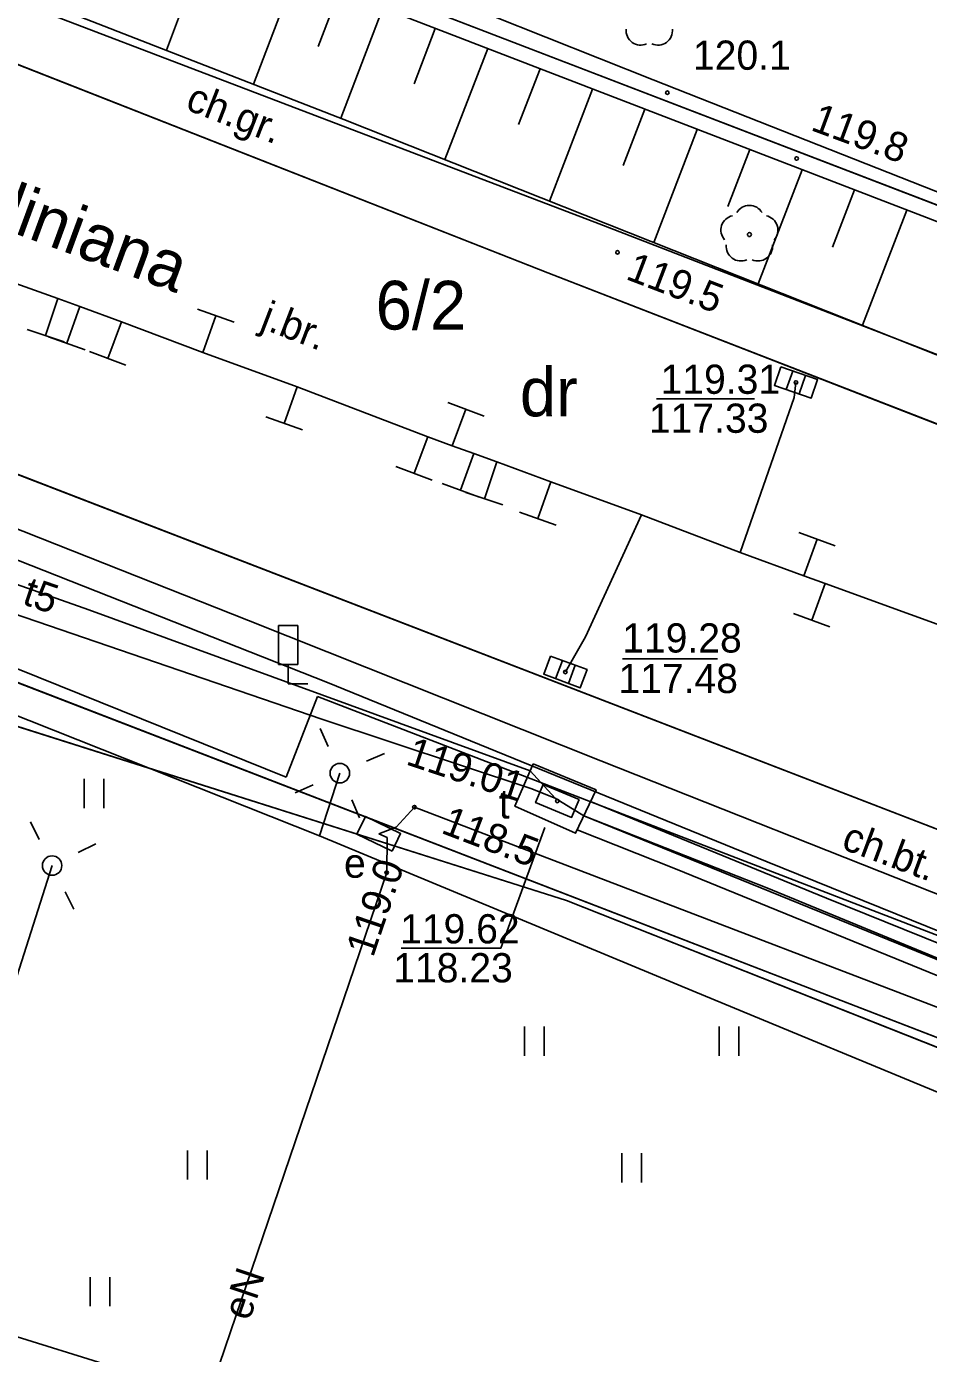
# Model space of a CAD drawing. Extents: x 6432121 to 6432331, y 5662538 to 5662686.
# Drawn here: x 6432202.58 to 6432225.74, y 5662569.04 to 5662603.09 of the extents above; entities that cross this region are included whole.
import ezdxf

# ---------------------------------------------------------------- set-up
doc = ezdxf.new("R2010")
doc.units = 0
for name, color, linetype in [('Warstwa 1', 7, 'Continuous'), ('Warstwa 10', 7, 'Continuous'), ('Warstwa 11', 7, 'Continuous'), ('Warstwa 12', 7, 'Continuous'), ('Warstwa 13', 7, 'Continuous'), ('Warstwa 14', 7, 'Continuous'), ('Warstwa 15', 7, 'Continuous'), ('Warstwa 16', 7, 'Continuous'), ('Warstwa 19', 7, 'Continuous'), ('Warstwa 2', 7, 'Continuous'), ('Warstwa 20', 7, 'Continuous'), ('Warstwa 21', 7, 'Continuous'), ('Warstwa 30', 7, 'Continuous'), ('Warstwa 4', 7, 'Continuous'), ('Warstwa 5', 7, 'Continuous'), ('Warstwa 6', 7, 'Continuous'), ('Warstwa 61', 7, 'Continuous'), ('Warstwa 8', 7, 'Continuous'), ('Warstwa 9', 7, 'Continuous')]:
    doc.layers.add(name, color=color, linetype=linetype)

msp = doc.modelspace()

# ---------------------------------------------------------------- linework, layer by layer
at = {"layer": 'Warstwa 1'}
for p, q in [((6432180.9, 5662615.82), (6432259.074, 5662585.787)), ((6432180.9, 5662615.82), (6432259.074, 5662585.787)), ((6432155.186, 5662604.45), (6432246.621, 5662569.177)), ((6432155.186, 5662604.45), (6432246.621, 5662569.177))]:
    msp.add_line(p, q, dxfattribs=at)
at = {"layer": 'Warstwa 10'}
for p, q in [((6432167.648, 5662617.501), (6432210.732, 5662600.706)), ((6432207.218, 5662605.272), (6432206.177, 5662602.481)), ((6432209.475, 5662604.416), (6432208.412, 5662601.611)), ((6432210.603, 5662603.989), (6432210.068, 5662602.581)), ((6432211.732, 5662603.561), (6432210.651, 5662600.738)), ((6432211.732, 5662603.561), (6432241.32, 5662592.163)), ((6432213.076, 5662603.042), (6432212.532, 5662601.625)), ((6432214.421, 5662602.525), (6432213.323, 5662599.677)), ((6432215.767, 5662602.007), (6432215.215, 5662600.576)), ((6432217.112, 5662601.488), (6432216.004, 5662598.614)), ((6432218.456, 5662600.971), (6432217.9, 5662599.527)), ((6432210.732, 5662600.706), (6432240.306, 5662588.971)), ((6432219.801, 5662600.453), (6432218.683, 5662597.551)), ((6432221.146, 5662599.934), (6432220.584, 5662598.477)), ((6432222.491, 5662599.416), (6432221.362, 5662596.487)), ((6432223.835, 5662598.897), (6432223.269, 5662597.426)), ((6432225.181, 5662598.38), (6432224.042, 5662595.424))]:
    msp.add_line(p, q, dxfattribs=at)
at = {"layer": 'Warstwa 11'}
msp.add_circle((6432221.139, 5662597.753), 0.05, dxfattribs=at)
for centre, start, end in [((6432218.35, 5662602.989), 174.1471, 293.8529), ((6432218.79, 5662602.989), 246.1471, 5.8529), ((6432221.139, 5662598.128), 30.1471, 149.8529), ((6432220.782, 5662597.869), 102.1471, 221.8529), ((6432221.496, 5662597.869), 318.1471, 77.8529), ((6432220.919, 5662597.45), 174.1471, 293.8529), ((6432221.359, 5662597.45), 246.1471, 5.8529)]:
    msp.add_arc(centre, 0.375, start, end, dxfattribs=at)
at = {"layer": 'Warstwa 12'}
for points in [[(6432151.934, 5662659.962), (6432163.647, 5662662.364), (6432165.031, 5662661.271), (6432166.026, 5662656.887), (6432167.998, 5662648.227), (6432170.198, 5662638.637), (6432172.215, 5662629.789), (6432174.2, 5662621.336), (6432174.764, 5662618.709), (6432176.004, 5662617.499), (6432181.388, 5662615.664), (6432187.493, 5662613.63), (6432194.563, 5662611.29), (6432209.024, 5662605.561), (6432218.668, 5662601.72), (6432230.17, 5662597.186), (6432236.4, 5662594.702), (6432238.551, 5662593.742), (6432242.89, 5662591.993), (6432244.915, 5662591.158), (6432249.823, 5662589.199), (6432255.518, 5662586.99), (6432264.175, 5662583.483)], [(6432156.818, 5662630.202), (6432158.039, 5662625.384), (6432159.105, 5662620.911), (6432168.554, 5662616.714), (6432182.01, 5662611.519), (6432201.034, 5662604.23), (6432217.284, 5662598.028), (6432236.124, 5662590.737), (6432242.639, 5662588.267), (6432252.12, 5662584.559), (6432258.988, 5662581.806), (6432263.17, 5662580.184), (6432269.496, 5662577.686)], [(6432244.915, 5662591.158), (6432242.89, 5662591.993), (6432238.551, 5662593.742), (6432237.475, 5662594.222), (6432236.4, 5662594.702), (6432230.17, 5662597.186), (6432224.419, 5662599.453), (6432218.668, 5662601.72), (6432209.024, 5662605.561), (6432194.563, 5662611.29), (6432187.493, 5662613.63), (6432176.004, 5662617.499), (6432174.764, 5662618.709), (6432174.2, 5662621.336), (6432172.215, 5662629.789)], [(6432127.185, 5662618.897), (6432135.629, 5662615.848), (6432142.79, 5662613.281), (6432154.997, 5662608.849), (6432160.46, 5662606.879), (6432165.736, 5662604.745), (6432167.852, 5662603.89), (6432175.869, 5662600.716), (6432188.607, 5662595.673), (6432197.141, 5662592.258), (6432208.285, 5662587.853), (6432217.328, 5662584.25), (6432226.269, 5662580.703), (6432229.116, 5662579.575), (6432234.631, 5662577.404), (6432234.076, 5662575.247), (6432232.817, 5662570.334), (6432230.472, 5662561.671), (6432228.926, 5662556.053)], [(6432228.367, 5662556.053), (6432231.658, 5662568.249), (6432233.96, 5662576.659), (6432221.597, 5662581.652), (6432210.31, 5662586.256), (6432196.752, 5662591.605), (6432184.96, 5662596.314), (6432169.081, 5662602.651), (6432160.264, 5662606.196), (6432148.936, 5662610.33), (6432147.827, 5662610.792), (6432135.842, 5662615.166), (6432127.959, 5662618.065)], [(6432125.976, 5662559.881), (6432127.22, 5662563.81), (6432133.93, 5662584.09), (6432142.61, 5662608.19), (6432143.204, 5662608.85), (6432144.41, 5662608.72), (6432156.66, 5662605.17), (6432161.55, 5662603.82), (6432185, 5662594.71), (6432189.43, 5662592.42), (6432210.16, 5662585.32), (6432215.53, 5662583.54), (6432216.154, 5662583.288)], [(6432192.41, 5662600.108), (6432193.356, 5662599.773), (6432194.036, 5662599.529), (6432199.301, 5662597.568), (6432201.822, 5662596.668), (6432203.384, 5662596.11), (6432203.955, 5662595.903), (6432205.017, 5662595.511), (6432207.109, 5662594.725), (6432209.534, 5662593.848), (6432212.881, 5662592.563), (6432213.507, 5662592.335), (6432214.063, 5662592.136), (6432214.654, 5662591.921), (6432216.043, 5662591.407), (6432218.372, 5662590.563)], [(6432222.334, 5662593.956), (6432222.29, 5662593.575), (6432220.899, 5662589.591)], [(6432191.954, 5662592.706), (6432192.888, 5662592.203), (6432198.702, 5662590.052), (6432204.186, 5662588.123), (6432211.524, 5662585.445), (6432215.512, 5662583.99), (6432216.154, 5662583.288)], [(6432216.415, 5662586.528), (6432216.935, 5662587.433), (6432218.372, 5662590.563)], [(6432218.372, 5662590.563), (6432220.899, 5662589.591)], [(6432220.899, 5662589.591), (6432222.533, 5662588.996), (6432223.084, 5662588.795), (6432227.467, 5662587.21), (6432230.087, 5662586.231), (6432231.926, 5662585.518), (6432233.915, 5662584.796), (6432234.582, 5662584.574), (6432241.702, 5662581.891), (6432242.178, 5662581.775), (6432243.336, 5662581.331), (6432246.139, 5662580.279)], [(6432243.948, 5662572.298), (6432242.135, 5662571.543), (6432241.053, 5662571.693), (6432238.493, 5662572.364), (6432237.277, 5662572.628), (6432233.344, 5662573.109), (6432232.791, 5662574.98), (6432232.085, 5662573.229), (6432226.752, 5662575.417), (6432219.763, 5662578.309), (6432210.104, 5662582.327), (6432202.024, 5662585.528)], [(6432210.626, 5662583.932), (6432210.104, 5662582.327)], [(6432211.625, 5662582.375), (6432212.075, 5662582.545), (6432212.54, 5662583.06), (6432231.41, 5662575.84), (6432233.01, 5662577.75), (6432233.44, 5662577.57), (6432244.03, 5662573.09), (6432248.15, 5662571.43), (6432248.19, 5662569.03), (6432263.02, 5662563.06), (6432265.27, 5662565.67), (6432270.61, 5662563.24), (6432271.806, 5662556.053)], [(6432286.865, 5662556.053), (6432280.878, 5662558.275), (6432269.835, 5662562.391), (6432267.557, 5662563.221), (6432266.199, 5662563.708), (6432264.885, 5662564.131), (6432253.393, 5662568.528), (6432242.726, 5662572.64), (6432236.197, 5662575.094), (6432234.863, 5662575.627), (6432233.503, 5662576.077), (6432221.588, 5662580.986), (6432216.891, 5662582.84), (6432216.154, 5662583.288)], [(6432211.625, 5662582.375), (6432211.84, 5662582.28), (6432211.83, 5662581.38), (6432203.66, 5662557.38), (6432203.3, 5662556.053)], [(6432203.24, 5662581.56), (6432199.79, 5662570.76), (6432198.72, 5662567.15), (6432185.3, 5662571.72)]]:
    msp.add_lwpolyline(points, dxfattribs=at)
at = {"layer": 'Warstwa 13'}
for centre in [(6432219.033, 5662601.394), (6432222.352, 5662599.706), (6432217.752, 5662597.297)]:
    msp.add_circle(centre, 0.045, dxfattribs=at)
at = {"layer": 'Warstwa 14'}
for p, q in [((6432218.758, 5662593.541), (6432221.271, 5662593.541)), ((6432217.883, 5662586.866), (6432220.317, 5662586.866))]:
    msp.add_line(p, q, dxfattribs=at)
msp.add_lwpolyline([(6432212.2, 5662579.438), (6432214.757, 5662579.438), (6432215.891, 5662582.541)], dxfattribs=at)
for centre in [(6432222.334, 5662593.956), (6432222.334, 5662593.956), (6432216.415, 5662586.528), (6432216.415, 5662586.528), (6432212.54, 5662583.06), (6432216.208, 5662583.218), (6432216.208, 5662583.218), (6432216.208, 5662583.218), (6432211.83, 5662581.38)]:
    msp.add_circle(centre, 0.045, dxfattribs=at)
at = {"layer": 'Warstwa 16'}
msp.add_lwpolyline([(6432215.591, 5662584.175), (6432217.205, 5662583.503), (6432216.678, 5662582.389), (6432215.121, 5662583.083)], close=True, dxfattribs=at)
at = {"layer": 'Warstwa 19'}
for p, q in [((6432203.384, 5662596.11), (6432203.074, 5662595.159)), ((6432203.955, 5662595.903), (6432203.616, 5662594.962)), ((6432206.971, 5662595.835), (6432207.914, 5662595.501)), ((6432207.109, 5662594.725), (6432207.443, 5662595.668)), ((6432203.549, 5662595.004), (6432202.598, 5662595.315)), ((6432205.017, 5662595.511), (6432204.668, 5662594.574)), ((6432204.086, 5662594.793), (6432203.146, 5662595.132)), ((6432205.136, 5662594.399), (6432204.199, 5662594.749)), ((6432209.534, 5662593.848), (6432209.195, 5662592.907)), ((6432213.395, 5662593.447), (6432214.33, 5662593.092)), ((6432213.507, 5662592.335), (6432213.863, 5662593.27)), ((6432209.666, 5662592.738), (6432208.725, 5662593.076)), ((6432212.881, 5662592.563), (6432212.53, 5662591.627)), ((6432214.063, 5662592.136), (6432213.719, 5662591.197)), ((6432214.654, 5662591.921), (6432214.338, 5662590.972)), ((6432212.998, 5662591.451), (6432212.062, 5662591.802)), ((6432214.188, 5662591.025), (6432213.25, 5662591.369)), ((6432216.043, 5662591.407), (6432215.708, 5662590.465)), ((6432214.812, 5662590.814), (6432213.864, 5662591.13)), ((6432216.179, 5662590.297), (6432215.237, 5662590.632)), ((6432222.405, 5662590.107), (6432223.345, 5662589.765)), ((6432222.533, 5662588.996), (6432222.875, 5662589.936)), ((6432223.084, 5662588.795), (6432222.739, 5662587.856)), ((6432223.208, 5662587.684), (6432222.27, 5662588.029))]:
    msp.add_line(p, q, dxfattribs=at)
at = {"layer": 'Warstwa 2'}
msp.add_lwpolyline([(6432249.029, 5662556.053), (6432246.97, 5662567.38), (6432245.21, 5662569.28), (6432216.44, 5662580.66), (6432197.427, 5662586.688)], dxfattribs=at)
for centre in [(6432210.626, 5662583.932), (6432203.24, 5662581.56)]:
    msp.add_circle(centre, 0.25, dxfattribs=at)
at = {"layer": 'Warstwa 20'}
msp.add_line((6432211.732, 5662603.561), (6432241.32, 5662592.163), dxfattribs=at)
at = {"layer": 'Warstwa 21'}
for p, q in [((6432167.648, 5662617.501), (6432210.732, 5662600.706)), ((6432210.732, 5662600.706), (6432240.306, 5662588.971))]:
    msp.add_line(p, q, dxfattribs=at)
msp.add_lwpolyline([(6432211.966, 5662581.932), (6432211.066, 5662582.368), (6432211.284, 5662582.818), (6432212.184, 5662582.382), (6432211.966, 5662581.932)], dxfattribs=at)
at = {"layer": 'Warstwa 30'}
for p, q in [((6432209.05, 5662587.72), (6432209.05, 5662586.72)), ((6432209.55, 5662587.72), (6432209.05, 5662587.72)), ((6432209.55, 5662586.72), (6432209.55, 5662587.72)), ((6432209.05, 5662586.72), (6432209.55, 5662586.72)), ((6432209.3, 5662586.22), (6432209.3, 5662586.72)), ((6432209.8, 5662586.22), (6432209.3, 5662586.22))]:
    msp.add_line(p, q, dxfattribs=at)
at = {"layer": 'Warstwa 4'}
for p, q in [((6432222.25, 5662594.249), (6432222.087, 5662593.776)), ((6432222.581, 5662594.136), (6432222.418, 5662593.663)), ((6432216.338, 5662586.823), (6432216.164, 5662586.355)), ((6432216.666, 5662586.701), (6432216.492, 5662586.233))]:
    msp.add_line(p, q, dxfattribs=at)
for points in [[(6432221.942, 5662594.355), (6432222.888, 5662594.03), (6432222.726, 5662593.557), (6432221.78, 5662593.882)], [(6432216.034, 5662586.937), (6432216.971, 5662586.588), (6432216.796, 5662586.119), (6432215.859, 5662586.468)], [(6432216.766, 5662583.259), (6432215.841, 5662583.64), (6432215.65, 5662583.177), (6432216.575, 5662582.796)]]:
    msp.add_lwpolyline(points, close=True, dxfattribs=at)
for points in [[(6432210.322, 5662584.618), (6432210.12, 5662585.075)], [(6432211.312, 5662584.236), (6432211.769, 5662584.438)], [(6432209.94, 5662583.628), (6432209.483, 5662583.426)], [(6432210.93, 5662583.246), (6432211.132, 5662582.789)], [(6432202.906, 5662582.232), (6432202.684, 5662582.679)], [(6432203.912, 5662581.894), (6432204.359, 5662582.116)], [(6432203.574, 5662580.888), (6432203.796, 5662580.441)]]:
    msp.add_lwpolyline(points, dxfattribs=at)
at = {"layer": 'Warstwa 5'}
for p, q in [((6432211.732, 5662603.561), (6432241.32, 5662592.163)), ((6432200.249, 5662587.452), (6432209.248, 5662583.832)), ((6432197.427, 5662586.688), (6432216.44, 5662580.66)), ((6432197.427, 5662586.688), (6432216.44, 5662580.66)), ((6432209.248, 5662583.832), (6432210.053, 5662585.902)), ((6432210.053, 5662585.902), (6432237.018, 5662575.504)), ((6432204.064, 5662583.034), (6432204.064, 5662583.784)), ((6432204.564, 5662583.034), (6432204.564, 5662583.784)), ((6432216.44, 5662580.66), (6432236.266, 5662572.818)), ((6432216.44, 5662580.66), (6432236.266, 5662572.818)), ((6432215.367, 5662576.678), (6432215.367, 5662577.428)), ((6432215.867, 5662576.678), (6432215.867, 5662577.428)), ((6432220.367, 5662576.678), (6432220.367, 5662577.428)), ((6432220.867, 5662576.678), (6432220.867, 5662577.428)), ((6432206.718, 5662573.501), (6432206.718, 5662574.251)), ((6432207.218, 5662573.501), (6432207.218, 5662574.251)), ((6432217.867, 5662573.428), (6432217.867, 5662574.178)), ((6432218.367, 5662573.428), (6432218.367, 5662574.178)), ((6432204.218, 5662570.251), (6432204.218, 5662571.001)), ((6432204.718, 5662570.251), (6432204.718, 5662571.001)), ((6432198.6, 5662570.62), (6432205.062, 5662568.622))]:
    msp.add_line(p, q, dxfattribs=at)
at = {"layer": 'Warstwa 6'}
for points in [[(6432259.074, 5662585.787), (6432263.163, 5662588.197), (6432246.69, 5662636.13), (6432228.29, 5662630.34), (6432193.86, 5662619.79), (6432180.9, 5662615.82)], [(6432180.9, 5662615.82), (6432147.05, 5662605.45), (6432141.907, 5662600.47), (6432155.186, 5662604.45), (6432246.621, 5662569.177), (6432269.007, 5662560.534), (6432263.163, 5662588.197), (6432259.074, 5662585.787)]]:
    msp.add_lwpolyline(points, close=True, dxfattribs=at)
for points in [[(6432261.892, 5662579.254), (6432260.419, 5662579.482), (6432250.699, 5662583.246), (6432245.014, 5662585.481), (6432215.968, 5662596.774), (6432192.716, 5662605.904), (6432163.326, 5662617.343), (6432161.597, 5662617.988)], [(6432159.72, 5662608.085), (6432174.611, 5662602.284), (6432189.213, 5662596.666), (6432233.139, 5662579.721)], [(6432249.006, 5662556.053), (6432246.621, 5662569.177), (6432155.186, 5662604.45), (6432141.907, 5662600.47), (6432128.788, 5662558.646), (6432132.46, 5662567.032), (6432163.983, 5662578.631), (6432172.647, 5662574.865), (6432180.454, 5662556.053)]]:
    msp.add_lwpolyline(points, dxfattribs=at)
at = {"layer": 'Warstwa 61'}
msp.add_lwpolyline([(6432216.891, 5662582.84), (6432233.502, 5662576.077)], dxfattribs=at)
at = {"layer": 'Warstwa 8'}
for p, q in [((6432192.716, 5662605.904), (6432215.968, 5662596.774)), ((6432215.968, 5662596.774), (6432245.014, 5662585.481)), ((6432192.281, 5662595.483), (6432233.139, 5662579.721))]:
    msp.add_line(p, q, dxfattribs=at)
for points in [[(6432217.063, 5662583.204), (6432223.118, 5662580.727), (6432230.163, 5662577.884), (6432233.662, 5662576.437)], [(6432233.342, 5662575.717), (6432227.275, 5662578.197), (6432219.242, 5662581.477), (6432216.719, 5662582.476)]]:
    msp.add_lwpolyline(points, dxfattribs=at)
at = {"layer": 'Warstwa 9'}
for p, q in [((6432189.19, 5662609.104), (6432210.732, 5662600.706)), ((6432192.716, 5662605.904), (6432215.968, 5662596.774)), ((6432210.732, 5662600.706), (6432240.306, 5662588.971)), ((6432215.968, 5662596.774), (6432245.014, 5662585.481)), ((6432192.281, 5662595.483), (6432233.139, 5662579.721)), ((6432200.249, 5662587.452), (6432209.248, 5662583.832)), ((6432209.248, 5662583.832), (6432210.053, 5662585.902)), ((6432210.053, 5662585.902), (6432237.018, 5662575.504)), ((6432198.6, 5662570.62), (6432205.062, 5662568.622))]:
    msp.add_line(p, q, dxfattribs=at)

# ---------------------------------------------------------------- texts
at = {"layer": 'Warstwa 13'}
msp.add_text('120.1', height=0.75, dxfattribs=at).set_placement((6432219.691, 5662601.982))
for s, rotation, p in [('119.8', 339.678, (6432222.685, 5662600.441)), ('119.5', 339.0535, (6432217.937, 5662596.619)), ('t5', 341.3167, (6432202.445, 5662588.279)), ('eN', 71.2015, (6432208.302, 5662569.852))]:
    msp.add_text(s, height=0.75, rotation=rotation, dxfattribs=at).set_placement(p)
at = {"layer": 'Warstwa 14'}
for s, height, rotation, p in [('Gliniana', 1.25, 339.8041, (6432200.68, 5662598.367)), ('119.01', 0.75, 341.6605, (6432212.292, 5662584.164)), ('118.5', 0.75, 339.065, (6432213.195, 5662582.407)), ('119.0', 0.75, 71.2015, (6432211.477, 5662579.181))]:
    msp.add_text(s, height=height, rotation=rotation, dxfattribs=at).set_placement(p)
for s, p in [('117.33', (6432218.56, 5662592.666)), ('117.48', (6432217.777, 5662585.987)), ('118.23', (6432211.998, 5662578.563))]:
    msp.add_text(s, height=0.75, dxfattribs=at).set_placement(p)
at = {"layer": 'Warstwa 15'}
for s, height, p in [('6/2', 1.25, (6432211.545, 5662595.316)), ('119.31', 0.75, (6432218.86, 5662593.666)), ('119.28', 0.75, (6432217.875, 5662587.027)), ('119.62', 0.75, (6432212.173, 5662579.563))]:
    msp.add_text(s, height=height, dxfattribs=at).set_placement(p)
at = {"layer": 'Warstwa 2'}
msp.add_text('dr', height=1.25, dxfattribs=at).set_placement((6432215.248, 5662593.088))
at = {"layer": 'Warstwa 21'}
msp.add_text('e', height=0.75, dxfattribs=at).set_placement((6432210.733, 5662581.248))
at = {"layer": 'Warstwa 5'}
msp.add_text('t', height=0.75, dxfattribs=at).set_placement((6432214.709, 5662582.768))
at = {"layer": 'Warstwa 8'}
msp.add_text('j.br.', height=0.75, rotation=338.9962, dxfattribs=at).set_placement((6432208.551, 5662595.365))
at = {"layer": 'Warstwa 9'}
for s, rotation, p in [('ch.gr.', 338.704, (6432206.631, 5662600.976)), ('ch.bt.', 339.6035, (6432223.469, 5662582.001))]:
    msp.add_text(s, height=0.75, rotation=rotation, dxfattribs=at).set_placement(p)

doc.saveas('drawing.dxf')
